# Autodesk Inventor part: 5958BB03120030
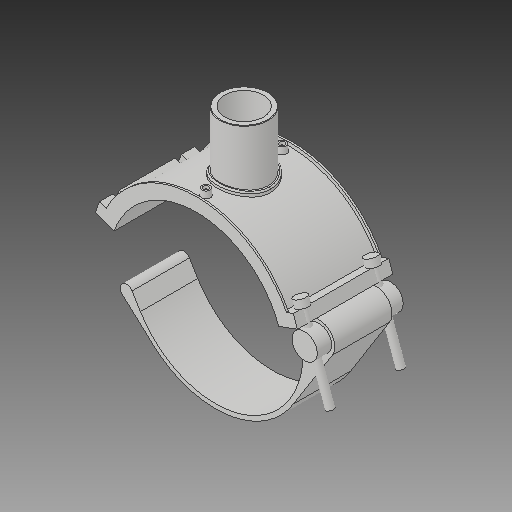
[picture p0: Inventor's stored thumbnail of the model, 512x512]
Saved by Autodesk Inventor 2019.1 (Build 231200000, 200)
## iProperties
Created: 2017-07
Part Number: 5958BB03120030
Material: Generic
Description: PLASSON BRANCH SADDLE 12'' x 3''
Document SubType Name: Modeling
Designer: KIM
Mass: 764.267 g
Surface Area: 1930.38 cm^2
Volume: 764.267 cm^3
Density: 1 g/cm^3
Appearance: Default
Author: KIM
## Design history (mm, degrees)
derived "5958B.ipt"
feature "Solid1::5958B.ipt"
feature "Solid2::5958B.ipt"
feature "Solid3::5958B.ipt"
tag "TaggingFeature1"
body "Solid1"
body "Solid2"
body "Solid3"
other parameters: "d_" = 323.4, "B_" = 180.594, "H_" = 106.934, "L_" = 176.022, "d_t" = 6, "d_1" = 88.7, "H_1" = 88.646, "d1" = 359.976, "d148" = 8.085, "d160" = 8.085, "d0" = 323.4, "d2" = 234.7722, "d3" = 80.85, "d4" = 176.022, "d5" = 0, "d6" = 0.1, "d8" = 0, "d19" = 6, "d20" = 6, "d21" = 105.6132, "d23" = 0, "d24" = 52.8066, "d26" = 0, "d27" = 3, "d28" = 3, "d29" = 3, "d30" = 107.8, "d31" = 6, "d32" = 0, "d33" = 0, "d34" = 0.6, "d40" = 187.18752, "d41" = 97.57, "d43" = 0, "d45" = 0, "d47" = 286.922, "d48" = 88.7, "d50" = 0, "d70" = 15, "d72" = 0, "d73" = 6, "d75" = 5, "d76" = 0, "d77" = 16.17, "d78" = 191.7, "d79" = 15, "d80" = 70.4088, "d82" = 5 deg, "d84" = 4, "d85" = 14, "d86" = 0, "d87" = 3, "d88" = 0, "d89" = 1, "d90" = 1, "d91" = 140.8176, "d92" = 0, "d93" = 0.5, "d94" = 170.21053, "d96" = 367.17552, "d97" = 3.52044, "d98" = 0, "d102" = 2.661, "d103" = 70.96, "d105" = 0, "d109" = -35.64467, "d117" = 0.887, "d120" = 140 deg, "d121" = 24.228, "d122" = 20 deg, "d123" = 719.952, "d124" = 215.9856, "d126" = 0, "d143" = 339.57, "d150" = 58.212, "d159" = 7.3152, "d161" = 8.085, "d162" = 105.6132, "d163" = 0, "d167" = 64.68, "d168" = 163.62545, "d173" = 1, "d175" = 161.7, "d176" = 20 deg, "d177" = 22.638, "d178" = 36.576, "d180" = 0, "d185" = 57.20715, "d186" = 57.20715, "d187" = 179.988, "d188" = 10.9728, "d189" = 22.638, "d190" = 0, "d191" = 269.982, "d200" = 18.288, "d202" = 0, "d216" = 158.4198, "d217" = 0, "d221" = 65.12814, "d222" = 22.638, "d223" = 13.5828, "d224" = 161.7, "d225" = 13.5828, "d227" = 46.5696, "d230" = 190.806, "d236" = 11.5 deg, "d238" = 20 deg, "d239" = 22.638, "d240" = 3.52044, "d241" = 0, "d242" = 6.468
